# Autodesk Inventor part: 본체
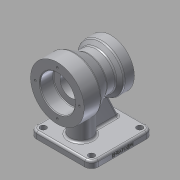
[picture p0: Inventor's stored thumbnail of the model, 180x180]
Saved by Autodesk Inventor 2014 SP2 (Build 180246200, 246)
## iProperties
Created: 2019-01
Part Number: 본체
Material: 알루미늄 6061
Document SubType Name: Modeling
Designer: CM-CAD
Density: 2.71 g/cm^3
Appearance: 알루미늄 - 평지
Mass: 902.144 g
Surface Area: 600.964 cm^2
Volume: 332.895 cm^3
Author: CM-CAD
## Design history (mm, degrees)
sketch "스케치1"
  geometry: L1 (-46, -46)-(46, -46); L2 (46, -46)-(46, 46); L3 (46, 46)-(-46, 46); L4 (-46, 46)-(-46, -46); L5 (-46, -46)-(46, 46); L6 (46, -46)-(-46, 46); 1 further point
  constraints: 12 end point, 2 midpoint, 2 parallel, 1 horizontal, 1 perpendicular
  dimensions: "d0" = 92 distance of L3.end L2.end; "d1" = 92 distance of L2.end L1.end
extrude "돌출1" new body sketch "스케치1" distance "d2" = 10; taper "d3" = 0 deg
sketch "스케치2"
  geometry: L1 (-46, -46)-(46, -46) reference; C1 r 16 at (0, -16); 1 further point
  constraints: 1 centre point
  dimensions: "d4" = 32 diameter of C1; "d5" = 30 distance from line of C1.centre L1
extrude "돌출2" join sketch "스케치2" distance "d6" = 70; taper "d7" = 0 deg
sketch "스케치3"
  geometry: L1 (0, 80)-(-32, 80) reference; L2 (-32, 10)-(-32, 80) reference; L3 (0, 10)-(0, 80) reference; L4 (46, 10)-(-46, 10) reference; L5 (-71.359, 80)-(65.608, 80); L6 (-51, 80)-(-51, 120); L7 (-51, 120)-(-26, 120); L8 (-26, 120)-(-5.215, 108); L9 (-5.215, 108)-(8.126, 108); L10 (8.126, 108)-(14, 115); L11 (14, 115)-(29, 115); L12 (29, 115)-(29, 80); L13 (-46, 0)-(-46, 10) reference; 1 further point
  constraints: 16 end point, 3 parallel, 3 perpendicular, 3 point on line, 1 collinear
  dimensions: "d8" = 80 diameter of L7 L5; "d9" = 5 distance between parallel lines of L6 L13; "d10" = 25 distance of L7.end L6.end; "d11" = 80 distance between parallel lines of L6 L12; "d12" = 15 distance from line of L10.end L12; "d13" = 56 diameter of L9 L5; "d14" = 30 deg angle of L8 L9; "d15" = 50 deg angle of L10 L9; "d16" = 70 diameter of L11 L5
revolve "회전1" sketch "스케치3" stored, may be unused: angle "d17" = 90 deg
sketch "스케치4"
  geometry: L1 (46, 10)-(-46, 10) reference; L2 (46, 0)-(46, 10) reference; L3 (14, 45)-(29, 45) reference; L4 (8.126, 52)-(14, 45) reference; L5 (0, 52)-(8.126, 52) reference; L6 (36, 10)-(10.93, 63.764); 1 further point
  constraints: 2 end point, 1 point on line
  dimensions: "d18" = 10 distance of L1.start L6.start; "d19" = 25 deg angle of L6 L2
feature "리브1" sketch "스케치4" dims "d20" = 1, "d21" = 10, "d22" = 0, "d23" = 0, "d24" = 1, "d25" = 1
fillet "모깎기1" dims "d26" = 10
hole "구멍1" diameter "d29" = 52; stored, may be unused: countersink angle "d33" = 90 deg, drill point angle "d35" = 0 deg; dims "d27" = 10, "d28" = 10, "d30" = 6, "d31" = 4, "d32" = 2, "d34" = 20
hole "구멍2" diameter "d38" = 32; stored, may be unused: countersink angle "d42" = 90 deg, drill point angle "d44" = 0 deg; dims "d39" = 6, "d40" = 4, "d41" = 2, "d43" = 43, "d45" = 10, "d46" = 10
hole "구멍3" diameter "d49" = 40; stored, may be unused: countersink angle "d53" = 90 deg, drill point angle "d55" = 0 deg; dims "d47" = 10, "d48" = 10, "d50" = 6, "d51" = 4, "d52" = 2, "d54" = 17
sketch "스케치5"
  geometry: C1 r 26 at (0, 0) reference; 2 further points
  dimensions: "d56" = 33 distance of point (0, 33) C1.centre
hole "구멍4" sketch "스케치5" at (0, 33) diameter "d57" = 3.242; stored, may be unused: countersink angle "d61" = 90 deg, drill point angle "d63" = 118 deg; dims "d58" = 9, "d59" = 4, "d60" = 2, "d62" = 11
sketch "스케치6"
  geometry: C1 r 20 at (0, 0) reference; 2 further points
  dimensions: "d67" = 27.5 distance of point (0, -27.5) C1.centre
hole "구멍5" sketch "스케치6" at (0, -27.5) diameter "d68" = 3.242; stored, may be unused: countersink angle "d72" = 90 deg, drill point angle "d74" = 118 deg; dims "d69" = 9, "d70" = 4, "d71" = 2, "d73" = 11
sketch "스케치7"
  geometry: A1 r 10 centre (-36, 36) between (-36, 46) and (-46, 36) reference; A2 r 10 centre (36, 36) between (46, 36) and (36, 46) reference; 3 further points
  constraints: 2 coincident
hole "구멍6" sketch "스케치7" at (-36, 36), (36, 36) diameter "d78" = 9; stored, may be unused: countersink angle "d82" = 90 deg, drill point angle "d84" = 0 deg; dims "d79" = 9, "d80" = 4, "d81" = 2, "d83" = 11
fillet "모깎기2" dims "d85" = 1
fillet "모깎기3" dims "d86" = 0.6
fillet "모깎기4" dims "d87" = 3
fillet "모깎기5" dims "d88" = 3
chamfer "모따기1" distance "d90" = 1; stored, may be unused: second distance "d91" = 2, angle "d92" = 45 deg
sketch "스케치8"
  geometry: L1 (-4.447, 19.686)-(-4.447, 52.87); L2 (-4.447, 52.87)-(-4.038, 52.87); L3 (-4.038, 52.87)-(-4.038, 19.686); L4 (-4.038, 19.686)-(-4.447, 19.686); 1 further point
  constraints: 2 other
feature "엠보싱1" sketch "스케치8" dims "d0" = 92, "d1" = 92, "d93" = 0.5, "d94" = 0
fillet "모깎기7" dims "d95" = 3
fillet "모깎기8" dims "d96" = 3
node "솔리드1"
pattern_circular "원형 패턴1" dims angle "d65" = 360 deg
pattern_circular "원형 패턴2" dims angle "d76" = 360 deg
mirror "대칭1"
